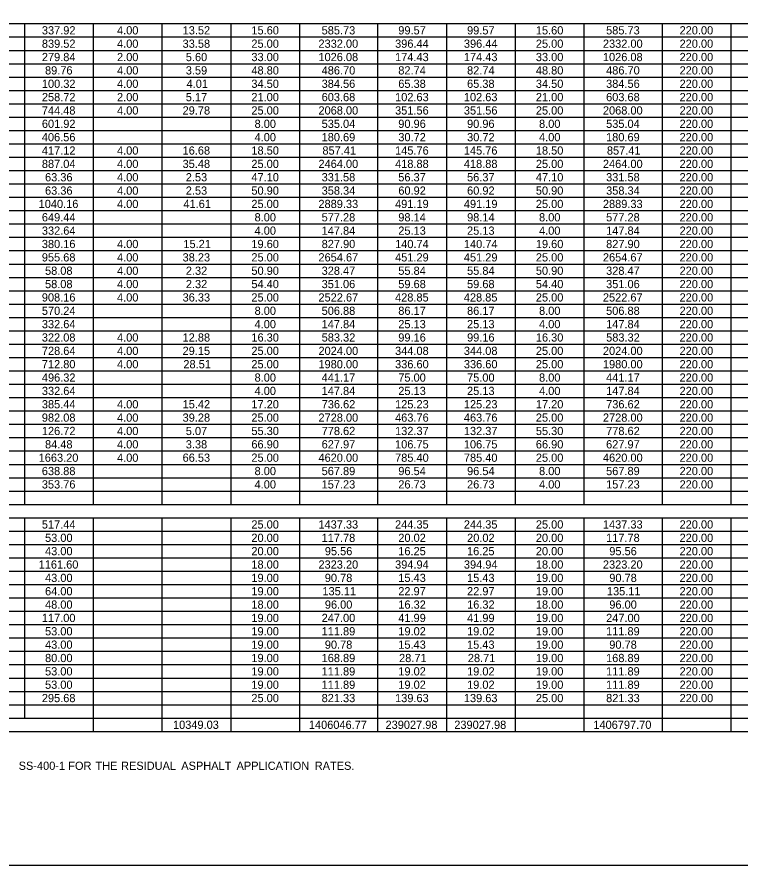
# Model space of a CAD drawing. Extents: x 2261867 to 2275370, y -3124789 to -3122260.
# Drawn here: x 2269764 to 2270239, y -3124789 to -3124232 of the extents above; entities that cross this region are included whole.
import ezdxf

# ---------------------------------------------------------------- set-up
doc = ezdxf.new("R2010")
doc.units = 0
doc.layers.add('Default', color=7, linetype='Continuous')
doc.layers.add('DSN_DRFT_Named-Boundary', color=7, linetype='Continuous')

msp = doc.modelspace()

# ---------------------------------------------------------------- linework, layer by layer
at = {"layer": 'Default'}
for p, q in [((2269400.16, -3124236.52), (2270414.11, -3124236.52)), ((2269769.15, -3124552.42), (2269769.15, -3124236.52)), ((2269769.15, -3124552.42), (2269769.15, -3124236.52)), ((2269814.34, -3124552.42), (2269814.34, -3124236.52)), ((2269814.34, -3124552.42), (2269814.34, -3124236.52)), ((2269859.53, -3124552.42), (2269859.53, -3124236.52)), ((2269859.53, -3124552.42), (2269859.53, -3124236.52)), ((2269904.72, -3124552.42), (2269904.72, -3124236.52)), ((2269904.72, -3124552.42), (2269904.72, -3124236.52)), ((2269949.92, -3124552.42), (2269949.92, -3124236.52)), ((2269949.92, -3124552.42), (2269949.92, -3124236.52)), ((2270001.25, -3124552.42), (2270001.25, -3124236.52)), ((2270001.25, -3124552.42), (2270001.25, -3124236.52)), ((2270046.44, -3124552.42), (2270046.44, -3124236.52)), ((2270046.44, -3124552.42), (2270046.44, -3124236.52)), ((2270091.63, -3124552.42), (2270091.63, -3124236.52)), ((2270091.63, -3124552.42), (2270091.63, -3124236.52)), ((2270136.82, -3124552.42), (2270136.82, -3124236.52)), ((2270136.82, -3124552.42), (2270136.82, -3124236.52)), ((2270188.16, -3124552.42), (2270188.16, -3124236.52)), ((2270188.16, -3124552.42), (2270188.16, -3124236.52)), ((2270233.35, -3124552.42), (2270233.35, -3124236.52)), ((2270233.35, -3124552.42), (2270233.35, -3124236.52)), ((2269400.16, -3124245.29), (2270414.11, -3124245.29)), ((2269400.16, -3124254.07), (2270414.11, -3124254.07)), ((2269400.16, -3124262.84), (2270414.11, -3124262.84)), ((2269400.16, -3124271.62), (2270414.11, -3124271.62)), ((2269400.16, -3124280.39), (2270414.11, -3124280.39)), ((2269400.16, -3124289.17), (2270414.11, -3124289.17)), ((2269400.16, -3124297.94), (2270414.11, -3124297.94)), ((2269400.16, -3124306.72), (2270414.11, -3124306.72)), ((2269400.16, -3124315.49), (2270414.11, -3124315.49)), ((2269400.16, -3124324.27), (2270414.11, -3124324.27)), ((2269400.16, -3124333.04), (2270414.11, -3124333.04)), ((2269400.16, -3124341.82), (2270414.11, -3124341.82)), ((2269400.16, -3124350.59), (2270414.11, -3124350.59)), ((2269400.16, -3124359.37), (2270414.11, -3124359.37)), ((2269400.16, -3124368.14), (2270414.11, -3124368.14)), ((2269400.16, -3124376.92), (2270414.11, -3124376.92)), ((2269400.16, -3124385.69), (2270414.11, -3124385.69)), ((2269400.16, -3124394.47), (2270414.11, -3124394.47)), ((2269400.16, -3124403.24), (2270414.11, -3124403.24)), ((2269400.16, -3124412.02), (2270414.11, -3124412.02)), ((2269400.16, -3124420.79), (2270414.11, -3124420.79)), ((2269400.16, -3124429.57), (2270414.11, -3124429.57)), ((2269400.16, -3124438.34), (2270414.11, -3124438.34)), ((2269400.16, -3124447.12), (2270414.11, -3124447.12)), ((2269400.16, -3124455.89), (2270414.11, -3124455.89)), ((2269400.16, -3124464.67), (2270414.11, -3124464.67)), ((2269400.16, -3124473.44), (2270414.11, -3124473.44)), ((2269400.16, -3124482.22), (2270414.11, -3124482.22)), ((2269400.16, -3124490.99), (2270414.11, -3124490.99)), ((2269400.16, -3124499.77), (2270414.11, -3124499.77)), ((2269400.16, -3124508.54), (2270414.11, -3124508.54)), ((2269400.16, -3124517.32), (2270414.11, -3124517.32)), ((2269400.16, -3124526.09), (2270414.11, -3124526.09)), ((2269400.16, -3124534.87), (2270414.11, -3124534.87)), ((2269400.16, -3124543.64), (2270414.11, -3124543.64)), ((2269400.16, -3124552.42), (2270414.11, -3124552.42)), ((2269400.16, -3124552.42), (2270414.11, -3124552.42)), ((2269400.16, -3124561.19), (2270414.11, -3124561.19)), ((2269769.15, -3124692.82), (2269769.15, -3124561.19)), ((2269769.15, -3124692.82), (2269769.15, -3124561.19)), ((2269814.34, -3124587.52), (2269814.34, -3124561.19)), ((2269814.34, -3124701.59), (2269814.34, -3124561.19)), ((2269859.53, -3124684.04), (2269859.53, -3124561.19)), ((2269859.53, -3124701.59), (2269859.53, -3124561.19)), ((2269904.72, -3124587.52), (2269904.72, -3124561.19)), ((2269904.72, -3124701.59), (2269904.72, -3124561.19)), ((2269949.92, -3124701.59), (2269949.92, -3124561.19)), ((2269949.92, -3124701.59), (2269949.92, -3124561.19)), ((2270001.25, -3124684.04), (2270001.25, -3124561.19)), ((2270001.25, -3124701.59), (2270001.25, -3124561.19)), ((2270046.44, -3124684.04), (2270046.44, -3124561.19)), ((2270046.44, -3124701.59), (2270046.44, -3124561.19)), ((2270091.63, -3124692.82), (2270091.63, -3124561.19)), ((2270091.63, -3124701.59), (2270091.63, -3124561.19)), ((2270136.82, -3124701.59), (2270136.82, -3124561.19)), ((2270136.82, -3124701.59), (2270136.82, -3124561.19)), ((2270188.16, -3124701.59), (2270188.16, -3124561.19)), ((2270188.16, -3124701.59), (2270188.16, -3124561.19)), ((2270233.35, -3124701.59), (2270233.35, -3124561.19)), ((2270233.35, -3124701.59), (2270233.35, -3124561.19)), ((2269400.16, -3124569.97), (2270414.11, -3124569.97)), ((2269400.16, -3124578.74), (2270414.11, -3124578.74)), ((2269400.16, -3124587.52), (2270414.11, -3124587.52)), ((2269400.16, -3124596.29), (2270414.11, -3124596.29)), ((2269814.34, -3124675.27), (2269814.34, -3124596.29)), ((2269904.72, -3124675.27), (2269904.72, -3124596.29)), ((2269400.16, -3124605.07), (2270414.11, -3124605.07)), ((2269400.16, -3124613.84), (2270414.11, -3124613.84)), ((2269400.16, -3124622.62), (2270414.11, -3124622.62)), ((2269400.16, -3124631.39), (2270414.11, -3124631.39)), ((2269400.16, -3124640.17), (2270414.11, -3124640.17)), ((2269400.16, -3124648.94), (2270414.11, -3124648.94)), ((2269400.16, -3124657.72), (2270414.11, -3124657.72)), ((2269400.16, -3124666.49), (2270414.11, -3124666.49)), ((2269400.16, -3124675.27), (2270414.11, -3124675.27)), ((2269400.16, -3124684.04), (2270414.11, -3124684.04)), ((2269400.16, -3124692.82), (2270414.11, -3124692.82)), ((2269490.54, -3124692.82), (2269769.15, -3124692.82)), ((2269769.15, -3124692.82), (2269904.72, -3124692.82)), ((2269814.34, -3124701.59), (2269814.34, -3124692.82)), ((2269904.72, -3124692.82), (2269949.92, -3124692.82)), ((2269949.92, -3124692.82), (2270046.44, -3124692.82)), ((2270046.44, -3124692.82), (2270414.11, -3124692.82)), ((2269400.16, -3124701.59), (2270414.11, -3124701.59))]:
    msp.add_line(p, q, dxfattribs=at)
at = {"layer": 'DSN_DRFT_Named-Boundary'}
msp.add_lwpolyline([(2269094.64, -3124789.38), (2270719.64, -3124789.38), (2270719.64, -3123623.23), (2269094.64, -3123623.23)], close=True, dxfattribs=at)

# ---------------------------------------------------------------- texts
at = {"layer": 'Default'}
for s, p in [('337.92', (2269780.41, -3124243.61)), ('4.00', (2269829.78, -3124243.61)), ('13.52', (2269872.89, -3124243.61)), ('15.60', (2269918.07, -3124243.61)), ('585.73', (2269964.22, -3124243.61)), ('99.57', (2270014.58, -3124243.61)), ('99.57', (2270059.77, -3124243.61)), ('15.60', (2270104.97, -3124243.61)), ('585.73', (2270151.13, -3124243.61)), ('220.00', (2270199.4, -3124243.61)), ('839.52', (2269780.41, -3124252.38)), ('4.00', (2269829.78, -3124252.38)), ('33.58', (2269872.86, -3124252.38)), ('25.00', (2269918.07, -3124252.38)), ('2332.00', (2269962.13, -3124252.38)), ('396.44', (2270012.5, -3124252.38)), ('396.44', (2270057.69, -3124252.38)), ('25.00', (2270104.97, -3124252.38)), ('2332.00', (2270149.04, -3124252.38)), ('220.00', (2270199.4, -3124252.38)), ('279.84', (2269780.4, -3124261.16)), ('2.00', (2269829.78, -3124261.16)), ('5.60', (2269874.97, -3124261.16)), ('33.00', (2269918.07, -3124261.16)), ('1026.08', (2269962.12, -3124261.16)), ('174.43', (2270012.48, -3124261.16)), ('174.43', (2270057.67, -3124261.16)), ('33.00', (2270104.97, -3124261.16)), ('1026.08', (2270149.03, -3124261.16)), ('220.00', (2270199.4, -3124261.16)), ('89.76', (2269782.48, -3124269.93)), ('4.00', (2269829.78, -3124269.93)), ('3.59', (2269874.96, -3124269.93)), ('48.80', (2269918.07, -3124269.93)), ('486.70', (2269964.23, -3124269.93)), ('82.74', (2270014.59, -3124269.93)), ('82.74', (2270059.78, -3124269.93)), ('48.80', (2270104.97, -3124269.93)), ('486.70', (2270151.14, -3124269.93)), ('220.00', (2270199.4, -3124269.93)), ('100.32', (2269780.41, -3124278.71)), ('4.00', (2269829.78, -3124278.71)), ('4.01', (2269875.48, -3124278.71)), ('34.50', (2269918.07, -3124278.71)), ('384.56', (2269964.22, -3124278.71)), ('65.38', (2270014.58, -3124278.71)), ('65.38', (2270059.77, -3124278.71)), ('34.50', (2270104.97, -3124278.71)), ('384.56', (2270151.13, -3124278.71)), ('220.00', (2270199.4, -3124278.71)), ('258.72', (2269780.41, -3124287.48)), ('2.00', (2269829.78, -3124287.48)), ('5.17', (2269874.96, -3124287.48)), ('21.00', (2269918.07, -3124287.48)), ('603.68', (2269964.22, -3124287.48)), ('102.63', (2270012.48, -3124287.48)), ('102.63', (2270057.67, -3124287.48)), ('21.00', (2270104.97, -3124287.48)), ('603.68', (2270151.12, -3124287.48)), ('220.00', (2270199.4, -3124287.48)), ('744.48', (2269780.38, -3124296.26)), ('4.00', (2269829.78, -3124296.26)), ('29.78', (2269872.86, -3124296.26)), ('25.00', (2269918.07, -3124296.26)), ('2068.00', (2269962.13, -3124296.26)), ('351.56', (2270012.48, -3124296.26)), ('351.56', (2270057.67, -3124296.26)), ('25.00', (2270104.97, -3124296.26)), ('2068.00', (2270149.04, -3124296.26)), ('220.00', (2270199.4, -3124296.26)), ('601.92', (2269780.41, -3124305.03)), ('8.00', (2269920.16, -3124305.03)), ('535.04', (2269964.23, -3124305.03)), ('90.96', (2270014.58, -3124305.03)), ('90.96', (2270059.77, -3124305.03)), ('8.00', (2270107.07, -3124305.03)), ('535.04', (2270151.14, -3124305.03)), ('220.00', (2270199.4, -3124305.03)), ('406.56', (2269780.38, -3124313.81)), ('4.00', (2269920.16, -3124313.81)), ('180.69', (2269964.22, -3124313.81)), ('30.72', (2270014.61, -3124313.81)), ('30.72', (2270059.8, -3124313.81)), ('4.00', (2270107.07, -3124313.81)), ('180.69', (2270151.12, -3124313.81)), ('220.00', (2270199.4, -3124313.81)), ('417.12', (2269780.41, -3124322.58)), ('4.00', (2269829.78, -3124322.58)), ('16.68', (2269872.86, -3124322.58)), ('18.50', (2269918.07, -3124322.58)), ('857.41', (2269964.74, -3124322.58)), ('145.76', (2270012.48, -3124322.58)), ('145.76', (2270057.67, -3124322.58)), ('18.50', (2270104.97, -3124322.58)), ('857.41', (2270151.65, -3124322.58)), ('220.00', (2270199.4, -3124322.58)), ('887.04', (2269780.4, -3124331.36)), ('4.00', (2269829.78, -3124331.36)), ('35.48', (2269872.86, -3124331.36)), ('25.00', (2269918.07, -3124331.36)), ('2464.00', (2269962.13, -3124331.36)), ('418.88', (2270012.48, -3124331.36)), ('418.88', (2270057.67, -3124331.36)), ('25.00', (2270104.97, -3124331.36)), ('2464.00', (2270149.04, -3124331.36)), ('220.00', (2270199.4, -3124331.36)), ('63.36', (2269782.48, -3124340.13)), ('4.00', (2269829.78, -3124340.13)), ('2.53', (2269874.96, -3124340.13)), ('47.10', (2269918.07, -3124340.13)), ('331.58', (2269964.22, -3124340.13)), ('56.37', (2270014.58, -3124340.13)), ('56.37', (2270059.77, -3124340.13)), ('47.10', (2270104.97, -3124340.13)), ('331.58', (2270151.12, -3124340.13)), ('220.00', (2270199.4, -3124340.13)), ('63.36', (2269782.48, -3124348.91)), ('4.00', (2269829.78, -3124348.91)), ('2.53', (2269874.96, -3124348.91)), ('50.90', (2269918.07, -3124348.91)), ('358.34', (2269964.23, -3124348.91)), ('60.92', (2270014.61, -3124348.91)), ('60.92', (2270059.8, -3124348.91)), ('50.90', (2270104.97, -3124348.91)), ('358.34', (2270151.14, -3124348.91)), ('220.00', (2270199.4, -3124348.91)), ('1040.16', (2269778.29, -3124357.68)), ('4.00', (2269829.78, -3124357.68)), ('41.61', (2269873.39, -3124357.68)), ('25.00', (2269918.07, -3124357.68)), ('2889.33', (2269962.12, -3124357.68)), ('491.19', (2270012.48, -3124357.68)), ('491.19', (2270057.67, -3124357.68)), ('25.00', (2270104.97, -3124357.68)), ('2889.33', (2270149.03, -3124357.68)), ('220.00', (2270199.4, -3124357.68)), ('649.44', (2269780.4, -3124366.46)), ('8.00', (2269920.16, -3124366.46)), ('577.28', (2269964.22, -3124366.46)), ('98.14', (2270014.59, -3124366.46)), ('98.14', (2270059.78, -3124366.46)), ('8.00', (2270107.07, -3124366.46)), ('577.28', (2270151.12, -3124366.46)), ('220.00', (2270199.4, -3124366.46)), ('332.64', (2269780.4, -3124375.23)), ('4.00', (2269920.16, -3124375.23)), ('147.84', (2269964.23, -3124375.23)), ('25.13', (2270014.58, -3124375.23)), ('25.13', (2270059.77, -3124375.23)), ('4.00', (2270107.07, -3124375.23)), ('147.84', (2270151.14, -3124375.23)), ('220.00', (2270199.4, -3124375.23)), ('380.16', (2269780.38, -3124384.01)), ('4.00', (2269829.78, -3124384.01)), ('15.21', (2269873.39, -3124384.01)), ('19.60', (2269918.07, -3124384.01)), ('827.90', (2269964.23, -3124384.01)), ('140.74', (2270012.5, -3124384.01)), ('140.74', (2270057.69, -3124384.01)), ('19.60', (2270104.97, -3124384.01)), ('827.90', (2270151.14, -3124384.01)), ('220.00', (2270199.4, -3124384.01)), ('955.68', (2269780.38, -3124392.78)), ('4.00', (2269829.78, -3124392.78)), ('38.23', (2269872.86, -3124392.78)), ('25.00', (2269918.07, -3124392.78)), ('2654.67', (2269962.12, -3124392.78)), ('451.29', (2270012.48, -3124392.78)), ('451.29', (2270057.67, -3124392.78)), ('25.00', (2270104.97, -3124392.78)), ('2654.67', (2270149.03, -3124392.78)), ('220.00', (2270199.4, -3124392.78)), ('58.08', (2269782.48, -3124401.56)), ('4.00', (2269829.78, -3124401.56)), ('2.32', (2269874.99, -3124401.56)), ('50.90', (2269918.07, -3124401.56)), ('328.47', (2269964.22, -3124401.56)), ('55.84', (2270014.59, -3124401.56)), ('55.84', (2270059.78, -3124401.56)), ('50.90', (2270104.97, -3124401.56)), ('328.47', (2270151.13, -3124401.56)), ('220.00', (2270199.4, -3124401.56)), ('58.08', (2269782.48, -3124410.33)), ('4.00', (2269829.78, -3124410.33)), ('2.32', (2269874.99, -3124410.33)), ('54.40', (2269918.07, -3124410.33)), ('351.06', (2269964.22, -3124410.33)), ('59.68', (2270014.58, -3124410.33)), ('59.68', (2270059.77, -3124410.33)), ('54.40', (2270104.97, -3124410.33)), ('351.06', (2270151.13, -3124410.33)), ('220.00', (2270199.4, -3124410.33)), ('908.16', (2269780.38, -3124419.11)), ('4.00', (2269829.78, -3124419.11)), ('36.33', (2269872.86, -3124419.11)), ('25.00', (2269918.07, -3124419.11)), ('2522.67', (2269962.12, -3124419.11)), ('428.85', (2270012.46, -3124419.11)), ('428.85', (2270057.65, -3124419.11)), ('25.00', (2270104.97, -3124419.11)), ('2522.67', (2270149.03, -3124419.11)), ('220.00', (2270199.4, -3124419.11)), ('570.24', (2269780.4, -3124427.88)), ('8.00', (2269920.16, -3124427.88)), ('506.88', (2269964.22, -3124427.88)), ('86.17', (2270014.58, -3124427.88)), ('86.17', (2270059.77, -3124427.88)), ('8.00', (2270107.07, -3124427.88)), ('506.88', (2270151.12, -3124427.88)), ('220.00', (2270199.4, -3124427.88)), ('332.64', (2269780.4, -3124436.66)), ('4.00', (2269920.16, -3124436.66)), ('147.84', (2269964.23, -3124436.66)), ('25.13', (2270014.58, -3124436.66)), ('25.13', (2270059.77, -3124436.66)), ('4.00', (2270107.07, -3124436.66)), ('147.84', (2270151.14, -3124436.66)), ('220.00', (2270199.4, -3124436.66)), ('322.08', (2269780.38, -3124445.43)), ('4.00', (2269829.78, -3124445.43)), ('12.88', (2269872.86, -3124445.43)), ('16.30', (2269918.07, -3124445.43)), ('583.32', (2269964.25, -3124445.43)), ('99.16', (2270014.58, -3124445.43)), ('99.16', (2270059.77, -3124445.43)), ('16.30', (2270104.97, -3124445.43)), ('583.32', (2270151.16, -3124445.43)), ('220.00', (2270199.4, -3124445.43)), ('728.64', (2269780.4, -3124454.21)), ('4.00', (2269829.78, -3124454.21)), ('29.15', (2269872.84, -3124454.21)), ('25.00', (2269918.07, -3124454.21)), ('2024.00', (2269962.13, -3124454.21)), ('344.08', (2270012.48, -3124454.21)), ('344.08', (2270057.67, -3124454.21)), ('25.00', (2270104.97, -3124454.21)), ('2024.00', (2270149.04, -3124454.21)), ('220.00', (2270199.4, -3124454.21)), ('712.80', (2269780.39, -3124462.98)), ('4.00', (2269829.78, -3124462.98)), ('28.51', (2269873.39, -3124462.98)), ('25.00', (2269918.07, -3124462.98)), ('1980.00', (2269962.13, -3124462.98)), ('336.60', (2270012.49, -3124462.98)), ('336.60', (2270057.68, -3124462.98)), ('25.00', (2270104.97, -3124462.98)), ('1980.00', (2270149.04, -3124462.98)), ('220.00', (2270199.4, -3124462.98)), ('496.32', (2269780.41, -3124471.76)), ('8.00', (2269920.16, -3124471.76)), ('441.17', (2269964.22, -3124471.76)), ('75.00', (2270014.59, -3124471.76)), ('75.00', (2270059.78, -3124471.76)), ('8.00', (2270107.07, -3124471.76)), ('441.17', (2270151.13, -3124471.76)), ('220.00', (2270199.4, -3124471.76)), ('332.64', (2269780.4, -3124480.53)), ('4.00', (2269920.16, -3124480.53)), ('147.84', (2269964.23, -3124480.53)), ('25.13', (2270014.58, -3124480.53)), ('25.13', (2270059.77, -3124480.53)), ('4.00', (2270107.07, -3124480.53)), ('147.84', (2270151.14, -3124480.53)), ('220.00', (2270199.4, -3124480.53)), ('385.44', (2269780.4, -3124489.31)), ('4.00', (2269829.78, -3124489.31)), ('15.42', (2269872.89, -3124489.31)), ('17.20', (2269918.07, -3124489.31)), ('736.62', (2269964.25, -3124489.31)), ('125.23', (2270012.48, -3124489.31)), ('125.23', (2270057.67, -3124489.31)), ('17.20', (2270104.97, -3124489.31)), ('736.62', (2270151.16, -3124489.31)), ('220.00', (2270199.4, -3124489.31)), ('982.08', (2269780.38, -3124498.08)), ('4.00', (2269829.78, -3124498.08)), ('39.28', (2269872.86, -3124498.08)), ('25.00', (2269918.07, -3124498.08)), ('2728.00', (2269962.13, -3124498.08)), ('463.76', (2270012.48, -3124498.08)), ('463.76', (2270057.67, -3124498.08)), ('25.00', (2270104.97, -3124498.08)), ('2728.00', (2270149.04, -3124498.08)), ('220.00', (2270199.4, -3124498.08)), ('126.72', (2269780.41, -3124506.86)), ('4.00', (2269829.78, -3124506.86)), ('5.07', (2269874.96, -3124506.86)), ('55.30', (2269918.07, -3124506.86)), ('778.62', (2269964.25, -3124506.86)), ('132.37', (2270012.48, -3124506.86)), ('132.37', (2270057.67, -3124506.86)), ('55.30', (2270104.97, -3124506.86)), ('778.62', (2270151.16, -3124506.86)), ('220.00', (2270199.4, -3124506.86)), ('84.48', (2269782.48, -3124515.63)), ('4.00', (2269829.78, -3124515.63)), ('3.38', (2269874.96, -3124515.63)), ('66.90', (2269918.07, -3124515.63)), ('627.97', (2269964.22, -3124515.63)), ('106.75', (2270012.46, -3124515.63)), ('106.75', (2270057.65, -3124515.63)), ('66.90', (2270104.97, -3124515.63)), ('627.97', (2270151.13, -3124515.63)), ('220.00', (2270199.4, -3124515.63)), ('1663.20', (2269778.3, -3124524.41)), ('4.00', (2269829.78, -3124524.41)), ('66.53', (2269872.86, -3124524.41)), ('25.00', (2269918.07, -3124524.41)), ('4620.00', (2269962.13, -3124524.41)), ('785.40', (2270012.49, -3124524.41)), ('785.40', (2270057.68, -3124524.41)), ('25.00', (2270104.97, -3124524.41)), ('4620.00', (2270149.04, -3124524.41)), ('220.00', (2270199.4, -3124524.41)), ('638.88', (2269780.38, -3124533.18)), ('8.00', (2269920.16, -3124533.18)), ('567.89', (2269964.22, -3124533.18)), ('96.54', (2270014.59, -3124533.18)), ('96.54', (2270059.78, -3124533.18)), ('8.00', (2270107.07, -3124533.18)), ('567.89', (2270151.12, -3124533.18)), ('220.00', (2270199.4, -3124533.18)), ('353.76', (2269780.38, -3124541.96)), ('4.00', (2269920.16, -3124541.96)), ('157.23', (2269964.22, -3124541.96)), ('26.73', (2270014.58, -3124541.96)), ('26.73', (2270059.77, -3124541.96)), ('4.00', (2270107.07, -3124541.96)), ('157.23', (2270151.13, -3124541.96)), ('220.00', (2270199.4, -3124541.96)), ('517.44', (2269780.4, -3124568.28)), ('25.00', (2269918.07, -3124568.28)), ('1437.33', (2269962.12, -3124568.28)), ('244.35', (2270012.46, -3124568.28)), ('244.35', (2270057.65, -3124568.28)), ('25.00', (2270104.97, -3124568.28)), ('1437.33', (2270149.03, -3124568.28)), ('220.00', (2270199.4, -3124568.28)), ('53.00', (2269782.49, -3124577.06)), ('20.00', (2269918.07, -3124577.06)), ('117.78', (2269964.22, -3124577.06)), ('20.02', (2270014.61, -3124577.06)), ('20.02', (2270059.8, -3124577.06)), ('20.00', (2270104.97, -3124577.06)), ('117.78', (2270151.12, -3124577.06)), ('220.00', (2270199.4, -3124577.06)), ('43.00', (2269782.49, -3124585.83)), ('20.00', (2269918.07, -3124585.83)), ('95.56', (2269966.32, -3124585.83)), ('16.25', (2270014.56, -3124585.83)), ('16.25', (2270059.75, -3124585.83)), ('20.00', (2270104.97, -3124585.83)), ('95.56', (2270153.22, -3124585.83)), ('220.00', (2270199.4, -3124585.83)), ('1161.60', (2269778.3, -3124594.61)), ('18.00', (2269918.07, -3124594.61)), ('2323.20', (2269962.13, -3124594.61)), ('394.94', (2270012.5, -3124594.61)), ('394.94', (2270057.69, -3124594.61)), ('18.00', (2270104.97, -3124594.61)), ('2323.20', (2270149.04, -3124594.61)), ('220.00', (2270199.4, -3124594.61)), ('43.00', (2269782.49, -3124603.38)), ('19.00', (2269918.07, -3124603.38)), ('90.78', (2269966.31, -3124603.38)), ('15.43', (2270014.58, -3124603.38)), ('15.43', (2270059.77, -3124603.38)), ('19.00', (2270104.97, -3124603.38)), ('90.78', (2270153.22, -3124603.38)), ('220.00', (2270199.4, -3124603.38)), ('64.00', (2269782.49, -3124612.16)), ('19.00', (2269918.07, -3124612.16)), ('135.11', (2269964.74, -3124612.16)), ('22.97', (2270014.58, -3124612.16)), ('22.97', (2270059.77, -3124612.16)), ('19.00', (2270104.97, -3124612.16)), ('135.11', (2270151.65, -3124612.16)), ('220.00', (2270199.4, -3124612.16)), ('48.00', (2269782.49, -3124620.93)), ('18.00', (2269918.07, -3124620.93)), ('96.00', (2269966.33, -3124620.93)), ('16.32', (2270014.61, -3124620.93)), ('16.32', (2270059.8, -3124620.93)), ('18.00', (2270104.97, -3124620.93)), ('96.00', (2270153.24, -3124620.93)), ('220.00', (2270199.4, -3124620.93)), ('117.00', (2269780.39, -3124629.71)), ('19.00', (2269918.07, -3124629.71)), ('247.00', (2269964.23, -3124629.71)), ('41.99', (2270014.58, -3124629.71)), ('41.99', (2270059.77, -3124629.71)), ('19.00', (2270104.97, -3124629.71)), ('247.00', (2270151.14, -3124629.71)), ('220.00', (2270199.4, -3124629.71)), ('53.00', (2269782.49, -3124638.48)), ('19.00', (2269918.07, -3124638.48)), ('111.89', (2269964.22, -3124638.48)), ('19.02', (2270014.61, -3124638.48)), ('19.02', (2270059.8, -3124638.48)), ('19.00', (2270104.97, -3124638.48)), ('111.89', (2270151.12, -3124638.48)), ('220.00', (2270199.4, -3124638.48)), ('43.00', (2269782.49, -3124647.26)), ('19.00', (2269918.07, -3124647.26)), ('90.78', (2269966.31, -3124647.26)), ('15.43', (2270014.58, -3124647.26)), ('15.43', (2270059.77, -3124647.26)), ('19.00', (2270104.97, -3124647.26)), ('90.78', (2270153.22, -3124647.26)), ('220.00', (2270199.4, -3124647.26)), ('80.00', (2269782.49, -3124656.03)), ('19.00', (2269918.07, -3124656.03)), ('168.89', (2269964.22, -3124656.03)), ('28.71', (2270015.1, -3124656.03)), ('28.71', (2270060.29, -3124656.03)), ('19.00', (2270104.97, -3124656.03)), ('168.89', (2270151.12, -3124656.03)), ('220.00', (2270199.4, -3124656.03)), ('53.00', (2269782.49, -3124664.81)), ('19.00', (2269918.07, -3124664.81)), ('111.89', (2269964.22, -3124664.81)), ('19.02', (2270014.61, -3124664.81)), ('19.02', (2270059.8, -3124664.81)), ('19.00', (2270104.97, -3124664.81)), ('111.89', (2270151.12, -3124664.81)), ('220.00', (2270199.4, -3124664.81)), ('53.00', (2269782.49, -3124673.58)), ('19.00', (2269918.07, -3124673.58)), ('111.89', (2269964.22, -3124673.58)), ('19.02', (2270014.61, -3124673.58)), ('19.02', (2270059.8, -3124673.58)), ('19.00', (2270104.97, -3124673.58)), ('111.89', (2270151.12, -3124673.58)), ('220.00', (2270199.4, -3124673.58)), ('295.68', (2269780.38, -3124682.36)), ('25.00', (2269918.07, -3124682.36)), ('821.33', (2269964.22, -3124682.36)), ('139.63', (2270012.48, -3124682.36)), ('139.63', (2270057.67, -3124682.36)), ('25.00', (2270104.97, -3124682.36)), ('821.33', (2270151.13, -3124682.36)), ('220.00', (2270199.4, -3124682.36)), ('10349.03', (2269866.56, -3124699.91)), ('1406046.77', (2269955.83, -3124699.91)), ('239027.98', (2270006.19, -3124699.91)), ('239027.98', (2270051.38, -3124699.91)), ('1406797.70', (2270142.75, -3124699.91)), (' SS-400-1', (2269763.14, -3124726.84)), (' FOR', (2269795.72, -3124726.84)), (' THE', (2269813.64, -3124726.84)), (' RESIDUAL', (2269830.42, -3124726.84)), (' ASPHALT', (2269869.99, -3124726.84)), (' APPLICATION', (2269906.32, -3124726.84)), (' RATES.', (2269957.69, -3124726.84))]:
    msp.add_text(s, height=5.4, dxfattribs=at).set_placement(p)

doc.saveas('drawing.dxf')
